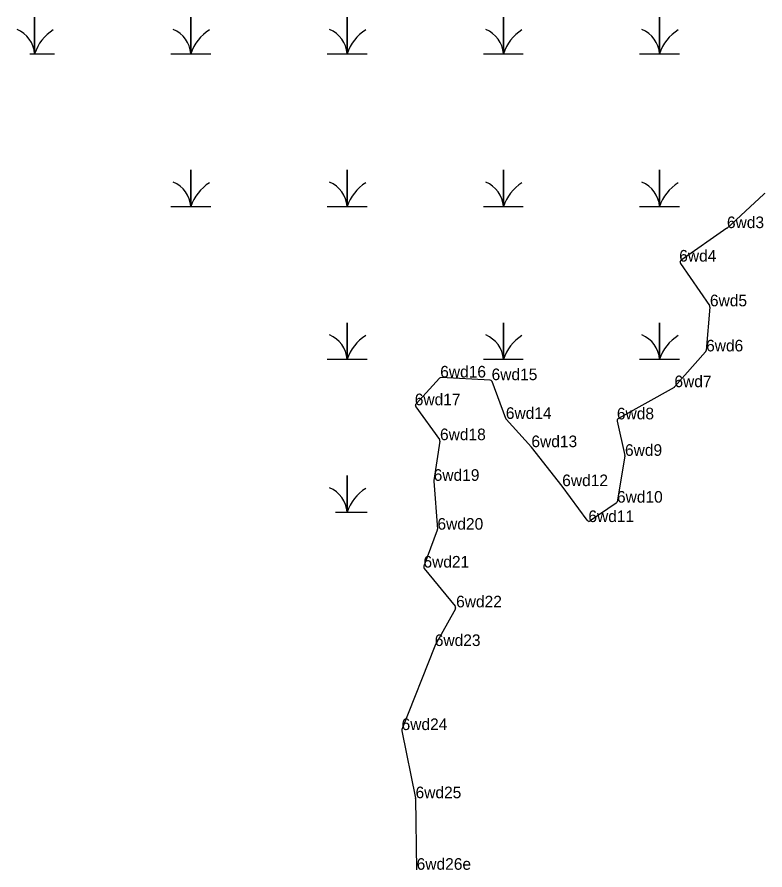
# Model space of a CAD drawing. Extents: x 2072529 to 2268796, y 436423 to 470397.
# Drawn here: x 2147688.4 to 2148010.3, y 442388.4 to 442755.6 of the extents above; entities that cross this region are included whole.
import ezdxf

# ---------------------------------------------------------------- set-up
doc = ezdxf.new("R2010")
doc.units = 0
for name, color, linetype in [('Exist Environmental Wetland Boundary', 7, 'Continuous'), ('Exist Environmental Wetland Boundary Cogo Comment', 7, 'Continuous'), ('Exist Environmental Wetland Boundary Cogo Point CELL', 7, 'Continuous'), ('Exist Hydro Swamp or Marsh', 7, 'Continuous')]:
    doc.layers.add(name, color=color, linetype=linetype)

msp = doc.modelspace()

# ---------------------------------------------------------------- linework, layer by layer
at = {"layer": 'Exist Environmental Wetland Boundary'}
for p, q in [((2148009.78, 442679.36), (2147993.97, 442664.76)), ((2147993.86, 442664.68), (2147974.19, 442650.89)), ((2147973.94, 442649.5), (2147986.4, 442631.36)), ((2147986.57, 442630.71), (2147984.98, 442611.97)), ((2147984.73, 442611.39), (2147971.42, 442596.36)), ((2147870.18, 442600.05), (2147860.09, 442589.05)), ((2147891.96, 442599.29), (2147870.97, 442600.37)), ((2147898.68, 442582.77), (2147892.85, 442598.63)), ((2147971.16, 442596.15), (2147947.2, 442582.74)), ((2147860.01, 442587.79), (2147870.17, 442573.74)), ((2147909.74, 442570.43), (2147898.88, 442582.44)), ((2147946.71, 442581.65), (2147950, 442566.85)), ((2147870.35, 442573.01), (2147867.71, 442556.02)), ((2147923, 442553.62), (2147909.78, 442570.38)), ((2147950.01, 442566.46), (2147946.65, 442546.92)), ((2147867.7, 442555.79), (2147869.29, 442535.09)), ((2147933.71, 442538.93), (2147923.03, 442553.59)), ((2147946.23, 442546.26), (2147935.08, 442538.69)), ((2147869.23, 442534.67), (2147863.48, 442519.09)), ((2147863.65, 442518.11), (2147876.92, 442501.95)), ((2147877.02, 442500.83), (2147868.19, 442484.83)), ((2147868.13, 442484.71), (2147853.99, 442448.85)), ((2147853.94, 442448.29), (2147859.88, 442419.32)), ((2147859.9, 442419.14), (2147860.36, 442388.42))]:
    msp.add_line(p, q, dxfattribs=at)
for centre, start, end in [((2148010.46, 442678.63), 100.6338, 132.7128), ((2147993.29, 442665.5), 305.0308, 312.7128), ((2147974.76, 442650.07), 125.0308, 214.4916), ((2147985.58, 442630.8), 355.1405, 34.4916), ((2147983.98, 442612.05), 318.4678, 355.1405), ((2147870.92, 442599.37), 87.0492, 137.442), ((2147891.91, 442598.29), 20.1838, 87.0492), ((2147970.67, 442597.02), 299.2407, 318.4678), ((2147860.82, 442588.38), 137.442, 215.8689), ((2147899.62, 442583.11), 200.1838, 222.1272), ((2147947.69, 442581.86), 119.2407, 192.5222), ((2147869.36, 442573.16), 351.1762, 35.8689), ((2147909, 442569.76), 38.2813, 42.1272), ((2147949.02, 442566.63), 350.2585, 12.5222), ((2147868.7, 442555.86), 171.1762, 184.3964), ((2147922.22, 442553), 36.0628, 38.2813), ((2147945.67, 442547.09), 304.1698, 350.2585), ((2147934.51, 442539.52), 216.0628, 304.1698), ((2147868.3, 442535.01), 339.7354, 4.3964), ((2147864.42, 442518.75), 159.7354, 219.3825), ((2147876.14, 442501.31), 331.1092, 39.3825), ((2147869.06, 442484.34), 151.1092, 158.4732), ((2147854.92, 442448.49), 158.4732, 191.5785), ((2147858.9, 442419.12), 0.8666, 11.5785)]:
    msp.add_arc(centre, 1, start, end, dxfattribs=at)
at = {"layer": 'Exist Environmental Wetland Boundary Cogo Point CELL'}
for p, q in [((2148010, 442679.56), (2148010, 442679.56)), ((2148010, 442679.56), (2148010, 442679.56)), ((2147993.92, 442664.72), (2147993.92, 442664.72)), ((2147973.38, 442650.32), (2147973.38, 442650.32)), ((2147973.38, 442650.32), (2147973.38, 442650.32)), ((2147986.6, 442631.07), (2147986.6, 442631.07)), ((2147984.95, 442611.64), (2147984.95, 442611.64)), ((2147984.95, 442611.64), (2147984.95, 442611.64)), ((2147870.5, 442600.39), (2147870.5, 442600.39)), ((2147870.5, 442600.39), (2147870.5, 442600.39)), ((2147892.62, 442599.25), (2147892.62, 442599.25)), ((2147971.31, 442596.23), (2147971.31, 442596.23)), ((2147859.54, 442588.45), (2147859.54, 442588.45)), ((2147898.75, 442582.58), (2147898.75, 442582.58)), ((2147898.75, 442582.58), (2147898.75, 442582.58)), ((2147946.55, 442582.37), (2147946.55, 442582.37)), ((2147946.55, 442582.37), (2147946.55, 442582.37)), ((2147870.41, 442573.41), (2147870.41, 442573.41)), ((2147870.41, 442573.41), (2147870.41, 442573.41)), ((2147909.76, 442570.4), (2147909.76, 442570.4)), ((2147950.04, 442566.66), (2147950.04, 442566.66)), ((2147867.69, 442555.9), (2147867.69, 442555.9)), ((2147923.02, 442553.61), (2147923.02, 442553.61)), ((2147923.02, 442553.61), (2147923.02, 442553.61)), ((2147946.58, 442546.5), (2147946.58, 442546.5)), ((2147946.58, 442546.5), (2147946.58, 442546.5)), ((2147934.28, 442538.15), (2147934.28, 442538.15)), ((2147869.31, 442534.87), (2147869.31, 442534.87)), ((2147869.31, 442534.87), (2147869.31, 442534.87)), ((2147863.29, 442518.55), (2147863.29, 442518.55)), ((2147877.35, 442501.42), (2147877.35, 442501.42)), ((2147877.35, 442501.42), (2147877.35, 442501.42)), ((2147868.16, 442484.77), (2147868.16, 442484.77)), ((2147853.88, 442448.58), (2147853.88, 442448.58)), ((2147853.88, 442448.58), (2147853.88, 442448.58)), ((2147859.89, 442419.23), (2147859.89, 442419.23)), ((2147860.36, 442388.42), (2147860.36, 442388.42)), ((2147860.36, 442388.42), (2147860.36, 442388.42))]:
    msp.add_line(p, q, dxfattribs=at)
at = {"layer": 'Exist Hydro Swamp or Marsh'}
for points in [[(2147693.8, 442739.83), (2147695.93, 442739.83), (2147695.93, 442755.61), (2147695.93, 442739.83), (2147704.53, 442739.83)], [(2147754.58, 442739.83), (2147763.18, 442739.83), (2147763.18, 442755.61), (2147763.18, 442739.83), (2147771.78, 442739.83)], [(2147821.83, 442739.83), (2147830.43, 442739.83), (2147830.43, 442755.61), (2147830.43, 442739.83), (2147839.03, 442739.83)], [(2147889.08, 442739.83), (2147897.68, 442739.83), (2147897.68, 442755.61), (2147897.68, 442739.83), (2147906.28, 442739.83)], [(2147956.33, 442739.83), (2147964.93, 442739.83), (2147964.93, 442755.61), (2147964.93, 442739.83), (2147973.53, 442739.83)], [(2147754.58, 442674.03), (2147763.18, 442674.03), (2147763.18, 442689.81), (2147763.18, 442674.03), (2147771.78, 442674.03)], [(2147821.83, 442674.03), (2147830.43, 442674.03), (2147830.43, 442689.81), (2147830.43, 442674.03), (2147839.03, 442674.03)], [(2147889.08, 442674.03), (2147897.68, 442674.03), (2147897.68, 442689.81), (2147897.68, 442674.03), (2147906.28, 442674.03)], [(2147956.33, 442674.03), (2147964.93, 442674.03), (2147964.93, 442689.81), (2147964.93, 442674.03), (2147973.53, 442674.03)], [(2147821.83, 442608.23), (2147830.43, 442608.23), (2147830.43, 442624.01), (2147830.43, 442608.23), (2147839.03, 442608.23)], [(2147889.08, 442608.23), (2147897.68, 442608.23), (2147897.68, 442624.01), (2147897.68, 442608.23), (2147906.28, 442608.23)], [(2147956.33, 442608.23), (2147964.93, 442608.23), (2147964.93, 442624.01), (2147964.93, 442608.23), (2147973.53, 442608.23)], [(2147825.41, 442542.43), (2147830.43, 442542.43), (2147830.43, 442558.21), (2147830.43, 442542.43), (2147839.03, 442542.43)]]:
    msp.add_lwpolyline(points, dxfattribs=at)
for centre, radius, start, end in [((2147683.66, 442738.94), 12.3, 4.1403, 67.535), ((2147714.17, 442733.77), 19.22, 122.1274, 161.6222), ((2147750.91, 442738.94), 12.3, 4.1403, 67.535), ((2147781.42, 442733.77), 19.22, 122.1274, 161.6222), ((2147818.16, 442738.94), 12.3, 4.1403, 67.535), ((2147848.67, 442733.77), 19.22, 122.1274, 161.6222), ((2147885.41, 442738.94), 12.3, 4.1403, 67.535), ((2147915.92, 442733.77), 19.22, 122.1274, 161.6222), ((2147952.66, 442738.94), 12.3, 4.1403, 67.535), ((2147983.17, 442733.77), 19.22, 122.1274, 161.6222), ((2147750.91, 442673.14), 12.3, 4.1403, 67.535), ((2147781.42, 442667.97), 19.22, 122.1274, 161.6222), ((2147818.16, 442673.14), 12.3, 4.1403, 67.535), ((2147848.67, 442667.97), 19.22, 122.1274, 161.6222), ((2147885.41, 442673.14), 12.3, 4.1403, 67.535), ((2147915.92, 442667.97), 19.22, 122.1274, 161.6222), ((2147952.66, 442673.14), 12.3, 4.1403, 67.535), ((2147983.17, 442667.97), 19.22, 122.1274, 161.6222), ((2147818.16, 442607.34), 12.3, 4.1403, 67.535), ((2147848.67, 442602.17), 19.22, 122.1274, 161.6222), ((2147885.41, 442607.34), 12.3, 4.1403, 67.535), ((2147915.92, 442602.17), 19.22, 122.1274, 161.6222), ((2147952.66, 442607.34), 12.3, 4.1403, 67.535), ((2147983.17, 442602.17), 19.22, 122.1274, 161.6222), ((2147818.16, 442541.54), 12.3, 4.1403, 67.535), ((2147848.67, 442536.37), 19.22, 122.1274, 161.6222)]:
    msp.add_arc(centre, radius, start, end, dxfattribs=at)

# ---------------------------------------------------------------- texts
at = {"layer": 'Exist Environmental Wetland Boundary Cogo Comment'}
for s, p in [('6wd3', (2147993.92, 442664.72)), ('6wd4', (2147973.38, 442650.32)), ('6wd5', (2147986.6, 442631.07)), ('6wd6', (2147984.95, 442611.64)), ('6wd16', (2147870.5, 442600.39)), ('6wd15', (2147892.62, 442599.25)), ('6wd7', (2147971.31, 442596.23)), ('6wd17', (2147859.54, 442588.45)), ('6wd14', (2147898.75, 442582.58)), ('6wd8', (2147946.55, 442582.37)), ('6wd18', (2147870.41, 442573.41)), ('6wd13', (2147909.76, 442570.4)), ('6wd9', (2147950.04, 442566.66)), ('6wd19', (2147867.69, 442555.9)), ('6wd12', (2147923.02, 442553.61)), ('6wd10', (2147946.58, 442546.5)), ('6wd11', (2147934.28, 442538.15)), ('6wd20', (2147869.31, 442534.87)), ('6wd21', (2147863.29, 442518.55)), ('6wd22', (2147877.35, 442501.42)), ('6wd23', (2147868.16, 442484.77)), ('6wd24', (2147853.88, 442448.58)), ('6wd25', (2147859.89, 442419.23)), ('6wd26e', (2147860.36, 442388.42))]:
    msp.add_text(s, height=5, dxfattribs=at).set_placement(p)

doc.saveas('drawing.dxf')
